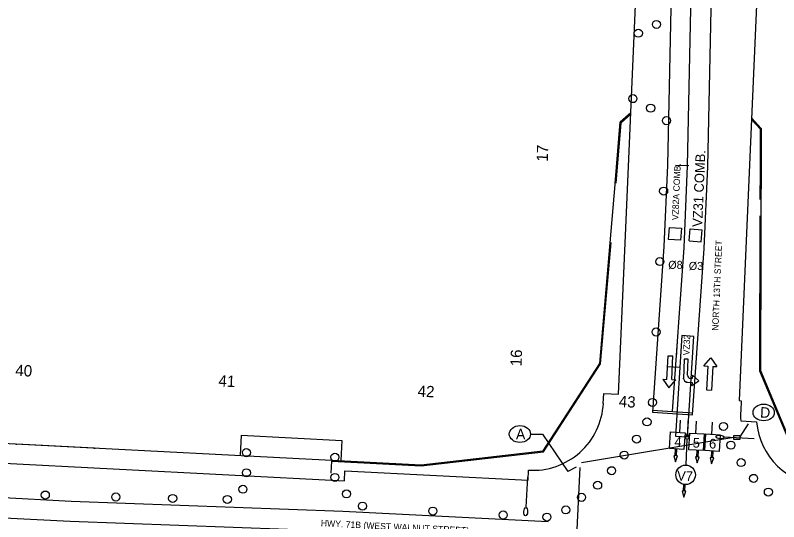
# Model space of a CAD drawing. Extents: x 0 to 1361828, y 0 to 1470398.
# Drawn here: x 683277 to 683656, y 735026.6 to 735277.9 of the extents above; entities that cross this region are included whole.
import ezdxf

# ---------------------------------------------------------------- set-up
doc = ezdxf.new("R2010")
doc.units = 0
for name, color, linetype in [('$', 7, 'Continuous'), ('Level 53', 7, 'Continuous'), ('MOT Stage 1', 7, 'Continuous'), ('MOT Stage 1 Lanes', 7, 'Continuous'), ('R_Horz Alg Station', 7, 'Continuous'), ('R_TYPE_A_CURB', 7, 'Continuous'), ('RW-EX', 7, 'Continuous'), ('RW-PR', 7, 'Continuous'), ('SIGNAL-EX', 7, 'Continuous'), ('SIGNAL-PLAN VIEW LABLES', 7, 'Continuous'), ('SIGNAL-PR', 7, 'Continuous'), ('TITEXT', 7, 'Continuous'), ('Video-Zones-pr', 7, 'Continuous')]:
    doc.layers.add(name, color=color, linetype=linetype)

# ---------------------------------------------------------------- blocks, each defined once
blk = doc.blocks.new('BAREL_1610')
at = {"layer": 'MOT Stage 1'}
blk.add_circle((0, 0.01), 2.88, dxfattribs=at)
blk = doc.blocks.new('BAREL_1611')
at = {"layer": 'MOT Stage 1'}
blk.add_circle((0, 0.01), 2.88, dxfattribs=at)
blk = doc.blocks.new('BAREL_1612')
at = {"layer": 'MOT Stage 1'}
blk.add_circle((0, 0.01), 2.88, dxfattribs=at)
blk = doc.blocks.new('BAREL_1613')
at = {"layer": 'MOT Stage 1'}
blk.add_circle((0, 0.01), 2.88, dxfattribs=at)
blk = doc.blocks.new('BAREL_1614')
at = {"layer": 'MOT Stage 1'}
blk.add_circle((0, 0.01), 2.88, dxfattribs=at)
blk = doc.blocks.new('BAREL_1654')
at = {"layer": 'MOT Stage 1'}
blk.add_circle((0, 0.01), 2.88, dxfattribs=at)
blk = doc.blocks.new('BAREL_1655')
at = {"layer": 'MOT Stage 1'}
blk.add_circle((0, 0.01), 2.88, dxfattribs=at)
blk = doc.blocks.new('BAREL_1656')
at = {"layer": 'MOT Stage 1'}
blk.add_circle((0, 0.01), 2.88, dxfattribs=at)
blk = doc.blocks.new('BAREL_1657')
at = {"layer": 'MOT Stage 1'}
blk.add_circle((0, 0.01), 2.88, dxfattribs=at)
blk = doc.blocks.new('BAREL_1658')
at = {"layer": 'MOT Stage 1'}
blk.add_circle((0, 0.01), 2.88, dxfattribs=at)
blk = doc.blocks.new('BAREL_1672')
at = {"layer": 'MOT Stage 1'}
blk.add_circle((0, 0.01), 2.88, dxfattribs=at)
blk = doc.blocks.new('BAREL_1673')
at = {"layer": 'MOT Stage 1'}
blk.add_circle((0, 0.01), 2.88, dxfattribs=at)
blk = doc.blocks.new('BAREL_1674')
at = {"layer": 'MOT Stage 1'}
blk.add_circle((0, 0.01), 2.88, dxfattribs=at)
blk = doc.blocks.new('BAREL_1675')
at = {"layer": 'MOT Stage 1'}
blk.add_circle((0, 0.01), 2.88, dxfattribs=at)
blk = doc.blocks.new('BAREL_1676')
at = {"layer": 'MOT Stage 1'}
blk.add_circle((0, 0.01), 2.88, dxfattribs=at)
blk = doc.blocks.new('BAREL_1677')
at = {"layer": 'MOT Stage 1'}
blk.add_circle((0, 0.01), 2.88, dxfattribs=at)
blk = doc.blocks.new('BAREL_1678')
at = {"layer": 'MOT Stage 1'}
blk.add_circle((0, 0.01), 2.88, dxfattribs=at)
blk = doc.blocks.new('BAREL_1679')
at = {"layer": 'MOT Stage 1'}
blk.add_circle((0, 0.01), 2.88, dxfattribs=at)
blk = doc.blocks.new('BAREL_1680')
at = {"layer": 'MOT Stage 1'}
blk.add_circle((0, 0.01), 2.88, dxfattribs=at)
blk = doc.blocks.new('SARROW_205')
at = {"layer": 'MOT Stage 1'}
for p, q in [((-6, -29.42), (-6, 0)), ((0, 0), (-6, 0)), ((0, -29.42), (0, 0)), ((-6, -29.42), (-11, -29.42)), ((-3, -39.81), (-11, -29.42)), ((5, -29.42), (-3, -39.81)), ((5, -29.42), (0, -29.42))]:
    blk.add_line(p, q, dxfattribs=at)
blk = doc.blocks.new('SARROW_206')
at = {"layer": 'MOT Stage 1'}
for p, q in [((-6, -29.42), (-6, 0)), ((0, 0), (-6, 0)), ((0, -29.42), (0, 0)), ((-6, -29.42), (-11, -29.42)), ((-3, -39.81), (-11, -29.42)), ((5, -29.42), (-3, -39.81)), ((5, -29.42), (0, -29.42))]:
    blk.add_line(p, q, dxfattribs=at)
blk = doc.blocks.new('BAREL_1708')
at = {"layer": 'MOT Stage 1'}
blk.add_circle((0, 0.01), 2.88, dxfattribs=at)
blk = doc.blocks.new('BAREL_1709')
at = {"layer": 'MOT Stage 1'}
blk.add_circle((0, 0.01), 2.88, dxfattribs=at)
blk = doc.blocks.new('BAREL_1710')
at = {"layer": 'MOT Stage 1'}
blk.add_circle((0, 0.01), 2.88, dxfattribs=at)
blk = doc.blocks.new('BAREL_1711')
at = {"layer": 'MOT Stage 1'}
blk.add_circle((0, 0.01), 2.88, dxfattribs=at)
blk = doc.blocks.new('BAREL_1712')
at = {"layer": 'MOT Stage 1'}
blk.add_circle((0, 0.01), 2.88, dxfattribs=at)
blk = doc.blocks.new('BAREL_1713')
at = {"layer": 'MOT Stage 1'}
blk.add_circle((0, 0.01), 2.88, dxfattribs=at)
blk = doc.blocks.new('BAREL_1714')
at = {"layer": 'MOT Stage 1'}
blk.add_circle((0, 0.01), 2.88, dxfattribs=at)
blk = doc.blocks.new('BAREL_1715')
at = {"layer": 'MOT Stage 1'}
blk.add_circle((0, 0.01), 2.88, dxfattribs=at)
blk = doc.blocks.new('BAREL_1716')
at = {"layer": 'MOT Stage 1'}
blk.add_circle((0, 0.01), 2.88, dxfattribs=at)
blk = doc.blocks.new('BAREL_1717')
at = {"layer": 'MOT Stage 1'}
blk.add_circle((0, 0.01), 2.88, dxfattribs=at)
blk = doc.blocks.new('BAREL_1718')
at = {"layer": 'MOT Stage 1'}
blk.add_circle((0, 0.01), 2.88, dxfattribs=at)
blk = doc.blocks.new('BAREL_1719')
at = {"layer": 'MOT Stage 1'}
blk.add_circle((0, 0.01), 2.88, dxfattribs=at)
blk = doc.blocks.new('BAREL_1724')
at = {"layer": 'MOT Stage 1'}
blk.add_circle((0, 0.01), 2.88, dxfattribs=at)
blk = doc.blocks.new('BAREL_1725')
at = {"layer": 'MOT Stage 1'}
blk.add_circle((0, 0.01), 2.88, dxfattribs=at)
blk = doc.blocks.new('BAREL_1726')
at = {"layer": 'MOT Stage 1'}
blk.add_circle((0, 0.01), 2.88, dxfattribs=at)
blk = doc.blocks.new('BAREL_1727')
at = {"layer": 'MOT Stage 1'}
blk.add_circle((0, 0.01), 2.88, dxfattribs=at)

msp = doc.modelspace()

# ---------------------------------------------------------------- linework, layer by layer
at = {"layer": 'Level 53'}
for p, q in [((683605.17, 735108.34), (683605.71, 735116.09)), ((683605.21, 735108.97), (683605.71, 735116.11)), ((683615.14, 735107.49), (683615.69, 735115.39))]:
    msp.add_line(p, q, dxfattribs=at)
at = {"layer": 'MOT Stage 1'}
for points in [[(683609.12, 735107.33), (683608.69, 735097.56), (683608.71, 735097.88)], [(683610.7, 735099.39), (683611.04, 735107.24), (683609.12, 735107.33)], [(683610.54, 735095.88), (683610.22, 735095.89), (683612.97, 735095.77), (683612.9, 735094.17), (683616.34, 735096.59), (683613.13, 735099.29), (683613.06, 735097.69), (683612.23, 735097.72)]]:
    msp.add_lwpolyline(points, dxfattribs=at)
for centre, radius in [((683610.63, 735097.79), 1.92), ((683612.29, 735099.32), 1.6)]:
    msp.add_arc(centre, radius, 177.5178, 267.5178, dxfattribs=at)
at = {"layer": 'MOT Stage 1 Lanes'}
for p, q in [((683124.65, 735046.17), (683304.73, 735036.86)), ((683124.13, 735036.18), (683304.21, 735026.87)), ((683304.73, 735036.86), (683439.64, 735031.89)), ((683439.64, 735031.89), (683541.55, 735026.66)), ((683304.21, 735026.87), (683439.13, 735021.9))]:
    msp.add_line(p, q, dxfattribs=at)
for points in [[(683604.91, 735398.45), (683600.74, 735203.61), (683598.98, 735163.25), (683593.24, 735081.04), (683613.19, 735079.65), (683618.95, 735162.12), (683620.73, 735202.96), (683624.91, 735398.02)], [(683603.28, 735081.34), (683608.96, 735162.68), (683610.73, 735203.28), (683614.91, 735398.23)], [(683593.31, 735082.04), (683613.26, 735080.64)]]:
    msp.add_lwpolyline(points, dxfattribs=at)
at = {"layer": 'R_Horz Alg Station'}
for points in [[(683604.74, 735203.6), (683611.4, 735203.31)], [(683600.38, 735103.7), (683607.04, 735103.4)]]:
    msp.add_lwpolyline(points, dxfattribs=at)
at = {"layer": 'R_TYPE_A_CURB'}
for p, q in [((683577.31, 735224.82), (683582.52, 735229.59)), ((683577.79, 735224.58), (683582.49, 735228.89)), ((683574.71, 735194.45), (683577.31, 735224.82)), ((683277.57, 735064.8), (683277.59, 735065.3)), ((683277.59, 735065.3), (683316.35, 735063.29)), ((683316.35, 735063.29), (683316.33, 735062.8))]:
    msp.add_line(p, q, dxfattribs=at)
for points in [[(683642.47, 735226.98), (683647.24, 735221.76), (683647.2, 735200.49)], [(683575.24, 735194.67), (683577.79, 735224.58)], [(683642.44, 735226.27), (683646.74, 735221.57), (683646.7, 735200.49)], [(683646.7, 735200.49), (683646.67, 735186.44)], [(683647.2, 735200.49), (683647.17, 735186.44)], [(683646.66, 735178.44), (683646.51, 735101.56), (683663.93, 735059.77), (683703.29, 735042.44), (683738.83, 735040.46), (683775.77, 735038.39)], [(683647.16, 735178.44), (683647.01, 735101.66), (683664.31, 735060.15), (683703.41, 735042.94), (683739.35, 735040.93), (683775.3, 735038.92)], [(683433.76, 735050.72), (683434.07, 735056.71), (683478.54, 735054.43), (683539.25, 735061.37), (683567.57, 735104.98), (683572.72, 735165.22)]]:
    msp.add_lwpolyline(points, dxfattribs=at)
at = {"layer": 'RW-EX'}
for p, q in [((683579.69, 735164.78), (683593.35, 735477.74)), ((683651.72, 735438.91), (683636.35, 735086.75)), ((683576.43, 735089.96), (683579.69, 735164.78)), ((683568.91, 735085.34), (683569.17, 735090.33)), ((683569.17, 735090.33), (683576.43, 735089.96)), ((683636.35, 735086.75), (683637.37, 735086.69)), ((683637.37, 735086.69), (683637.09, 735081.7)), ((683637.11, 735076.69), (683644.97, 735076.25)), ((682951.92, 735072.12), (683440.41, 735046.87)), ((683531.55, 735047.2), (683531.8, 735052.19)), ((683440.41, 735046.87), (683440.66, 735051.86)), ((683440.66, 735051.86), (683531.55, 735047.2))]:
    msp.add_line(p, q, dxfattribs=at)
for centre, radius, start, end in [((683533.96, 735087.13), 35, 266.468, 357.0668), ((683680.03, 735079.3), 43, 176.7989, 183.4763), ((683679.84, 735079.28), 35, 184.9566, 266.3951)]:
    msp.add_arc(centre, radius, start, end, dxfattribs=at)
at = {"layer": 'RW-PR'}
for p, q in [((683389.17, 735069.54), (683388.66, 735059.56)), ((683389.17, 735069.54), (683439.11, 735066.96)), ((683439.11, 735066.96), (683438.59, 735056.98))]:
    msp.add_line(p, q, dxfattribs=at)
for points in [[(683582.52, 735229.59), (683577.31, 735224.82), (683567.08, 735105.15), (683538.96, 735061.84)], [(683642.47, 735226.98), (683647.24, 735221.76), (683647.01, 735101.66), (683664.31, 735060.15)], [(682953.3, 735102.08), (682980.75, 735110.68), (682985.75, 735110.42), (682989.19, 735080.2), (683277.18, 735065.32), (683449.96, 735056.39), (683478.52, 735054.93), (683538.96, 735061.84)]]:
    msp.add_lwpolyline(points, dxfattribs=at)
at = {"layer": 'SIGNAL-EX'}
for points in [[(683640.74, 735075.18), (683636.7, 735068.73)], [(683633.68, 735068.46), (683558.1, 735055.78)], [(683555.49, 735053.7), (683551.34, 735051.57)], [(683553.48, 734971.62), (683557.44, 735053.56)]]:
    msp.add_lwpolyline(points, dxfattribs=at)
msp.add_lwpolyline([(683633.73, 735069.49), (683636.72, 735069.35), (683636.63, 735067.36), (683633.64, 735067.5)], close=True, dxfattribs=at)
at = {"layer": 'SIGNAL-PLAN VIEW LABLES'}
for points in [[(683606.99, 735077.02), (683606.68, 735070.89)], [(683610.86, 735076.77), (683610.62, 735070.65)], [(683614.98, 735076.51), (683614.66, 735070.41)], [(683622.96, 735076.01), (683622.65, 735069.98)], [(683532.78, 735070.07), (683538.78, 735070.07), (683551.34, 735051.57)], [(683610.3, 735067.7), (683609.79, 735054.76)], [(683604.44, 735059.37), (683603.93, 735059.4), (683604.7, 735056.4), (683605.78, 735059.3), (683605.28, 735059.33), (683605.45, 735062.68), (683604.61, 735062.73), (683604.44, 735059.37)], [(683604.61, 735062.73), (683604.44, 735059.37), (683603.93, 735059.4), (683604.7, 735056.4), (683605.78, 735059.3), (683605.28, 735059.33), (683605.45, 735062.68)], [(683615.22, 735058.74), (683614.72, 735058.77), (683615.49, 735055.77), (683616.56, 735058.67), (683616.06, 735058.7), (683616.23, 735062.05), (683615.39, 735062.1), (683615.22, 735058.74)], [(683615.39, 735062.1), (683615.22, 735058.74), (683614.72, 735058.77), (683615.49, 735055.77), (683616.56, 735058.67), (683616.06, 735058.7), (683616.23, 735062.05)], [(683622.37, 735058.35), (683621.87, 735058.38), (683622.64, 735055.39), (683623.71, 735058.29), (683623.21, 735058.31), (683623.38, 735061.67), (683622.54, 735061.71), (683622.37, 735058.35)], [(683622.54, 735061.71), (683622.37, 735058.35), (683621.87, 735058.38), (683622.64, 735055.39), (683623.71, 735058.29), (683623.21, 735058.31), (683623.38, 735061.67)], [(683608.58, 735041.83), (683608.08, 735041.85), (683608.91, 735038.87), (683609.93, 735041.79), (683609.42, 735041.8), (683609.53, 735045.16), (683608.69, 735045.19), (683608.58, 735041.83)], [(683608.69, 735045.19), (683608.58, 735041.83), (683608.08, 735041.85), (683608.91, 735038.87), (683609.93, 735041.79), (683609.42, 735041.8), (683609.53, 735045.16)]]:
    msp.add_lwpolyline(points, dxfattribs=at)
for points in [[(683608.93, 735062.48), (683601.8, 735062.9), (683602.29, 735071.15), (683609.48, 735070.72)], [(683610.62, 735070.65), (683611.54, 735067.64), (683609.46, 735067.74)], [(683618.43, 735061.92), (683611.31, 735062.34), (683611.8, 735070.59), (683618.99, 735070.16)], [(683626.42, 735061.49), (683619.3, 735061.91), (683619.79, 735070.16), (683626.98, 735069.73)]]:
    msp.add_lwpolyline(points, close=True, dxfattribs=at)
msp.add_circle((683609.76, 735049.91), 4.85, dxfattribs=at)
for centre in [(683648.5, 735080.87), (683527.51, 735070.13)]:
    msp.add_ellipse(centre, major_axis=(-5.27, 0), ratio=0.790685, dxfattribs=at)
at = {"layer": 'SIGNAL-PR'}
for p, q in [((683643.85, 735067.77), (683628.87, 735068.53)), ((683531.29, 735048.78), (683530.51, 735033.8))]:
    msp.add_line(p, q, dxfattribs=at)
for centre, major_axis in [((683626.85, 735068.64), (2.02, -0.1)), ((683530.4, 735031.6), (0.11, 2.02))]:
    msp.add_ellipse(centre, major_axis=major_axis, ratio=0.447722, dxfattribs=at)
at = {"layer": 'Video-Zones-pr'}
for points in [[(683607.29, 735166.27), (683601.3, 735166.69), (683601.72, 735172.67), (683607.7, 735172.25), (683607.29, 735166.27)], [(683611.54, 735165.97), (683611.96, 735171.96)], [(683611.96, 735171.96), (683617.94, 735171.54)], [(683617.52, 735165.55), (683617.94, 735171.54)], [(683611.54, 735165.97), (683617.52, 735165.55)]]:
    msp.add_lwpolyline(points, dxfattribs=at)
msp.add_lwpolyline([(683607.85, 735118.98), (683604.69, 735069.08), (683610.67, 735068.7), (683613.83, 735118.6)], close=True, dxfattribs=at)

# ---------------------------------------------------------------- block references
at = {"layer": 'MOT Stage 1'}
for name, p, xscale, yscale, rotation in [('BAREL_1727', (683595.28, 735273.39), 0.6945420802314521, 0.6945420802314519, 87.04179557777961), ('BAREL_1726', (683586.29, 735269.03), 0.6945420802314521, 0.6945420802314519, 87.04179557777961), ('BAREL_1725', (683583.6, 735236.56), 0.6945420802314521, 0.6945420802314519, 87.04179557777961), ('BAREL_1724', (683592.41, 735231.83), 0.6945420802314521, 0.6945420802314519, 87.04179557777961), ('BAREL_1719', (683600.25, 735225.63), 0.6945420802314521, 0.6945420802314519, 87.04179557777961), ('BAREL_1718', (683598.85, 735190.66), 0.6945420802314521, 0.6945420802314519, 87.04179557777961), ('BAREL_1717', (683596.99, 735155.71), 0.6945420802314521, 0.6945420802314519, 87.04179557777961), ('BAREL_1716', (683595.11, 735120.76), 0.6945420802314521, 0.6945420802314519, 87.04179557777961), ('SARROW_205', (683601.06, 735108.99), 0.4000000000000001, -0.4000000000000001, 177.22923073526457), ('SARROW_206', (683620.19, 735092.11), 0.3999999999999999, 0.3999999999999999, 176.69984902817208), ('BAREL_1715', (683593.31, 735085.8), 0.6945420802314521, 0.6945420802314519, 87.04179557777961), ('BAREL_1714', (683590.6, 735076.18), 0.6945420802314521, 0.6945420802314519, 87.04179557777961), ('BAREL_1658', (683628.56, 735073.9), 0.6945420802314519, 0.694542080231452, 102.17652807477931), ('BAREL_1713', (683585.42, 735067.62), 0.6945420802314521, 0.6945420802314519, 87.04179557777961), ('BAREL_1657', (683632.27, 735064.61), 0.6945420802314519, 0.694542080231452, 102.17652807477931), ('BAREL_1610', (683391.74, 735060.9), 0.6945420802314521, 0.6945420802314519, 87.04179557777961), ('BAREL_1611', (683435.68, 735058.63), 0.6945420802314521, 0.6945420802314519, 87.04179557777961), ('BAREL_1712', (683579.31, 735059.71), 0.6945420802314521, 0.6945420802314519, 87.04179557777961), ('BAREL_1656', (683637.29, 735055.97), 0.6945420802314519, 0.694542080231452, 102.17652807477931), ('BAREL_1612', (683391.74, 735050.9), 0.6945420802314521, 0.6945420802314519, 87.04179557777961), ('BAREL_1711', (683573.02, 735051.94), 0.6945420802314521, 0.6945420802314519, 87.04179557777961), ('BAREL_1614', (683435.68, 735048.63), 0.6945420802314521, 0.6945420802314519, 87.04179557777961), ('BAREL_1655', (683643.51, 735048.14), 0.6945420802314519, 0.694542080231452, 102.17652807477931), ('BAREL_1613', (683390.02, 735042.75), 0.6945420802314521, 0.6945420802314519, 87.04179557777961), ('BAREL_1710', (683566.09, 735044.72), 0.6945420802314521, 0.6945420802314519, 87.04179557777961), ('BAREL_1672', (683291.9, 735039.87), 0.6945420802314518, 0.6945420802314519, 116.71114235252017), ('BAREL_1673', (683326.89, 735038.91), 0.6945420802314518, 0.6945420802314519, 116.71114235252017), ('BAREL_1674', (683355.14, 735038.17), 0.6945420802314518, 0.6945420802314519, 116.71114235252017), ('BAREL_1676', (683441.43, 735040.45), 0.6945420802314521, 0.6945420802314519, 87.04179557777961), ('BAREL_1709', (683558.08, 735038.74), 0.6945420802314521, 0.6945420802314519, 87.04179557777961), ('BAREL_1654', (683650.85, 735041.34), 0.6945420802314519, 0.694542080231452, 102.17652807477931), ('BAREL_1675', (683382.26, 735037.71), 0.6945420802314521, 0.6945420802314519, 87.04179557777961), ('BAREL_1677', (683449.37, 735034.37), 0.6945420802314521, 0.6945420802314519, 87.04179557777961), ('BAREL_1678', (683484.29, 735031.91), 0.6945420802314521, 0.6945420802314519, 87.04179557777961), ('BAREL_1708', (683550.28, 735032.48), 0.6945420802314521, 0.6945420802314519, 87.04179557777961), ('BAREL_1679', (683519.23, 735029.97), 0.6945420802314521, 0.6945420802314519, 87.04179557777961), ('BAREL_1680', (683540.93, 735028.94), 0.6945420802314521, 0.6945420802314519, 87.04179557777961)]:
    msp.add_blockref(name, p, dxfattribs=dict(at, xscale=xscale, yscale=yscale, rotation=rotation))

# ---------------------------------------------------------------- texts
at = {"layer": '$'}
for s, height, rotation, p in [('17', 5.6, 88.3887, (683541.37, 735205.23)), ('VZ31 COMB.', 4.8, 87.5006, (683617.95, 735172.8)), ('VZ82A COMB.', 3.2, 87.5006, (683606.12, 735176.18)), ('NORTH 13TH STREET', 3.2, 87.5995, (683626.03, 735121.35)), ('VZ32', 3.2, 87.5006, (683611.65, 735109.11)), ('16', 5.6, 88.3887, (683528.36, 735103.71)), ('40', 5.6, 357.0415, (683276.92, 735099.04)), ('41', 5.6, 357.0415, (683377.75, 735093.83)), ('42', 5.6, 357.0415, (683476.63, 735088.74)), ('43', 5.6, 357.0415, (683576.49, 735083.61)), ('HWY. 71B (WEST WALNUT STREET)', 3.2, 357.0637, (683428.62, 735024.4))]:
    msp.add_text(s, height=height, rotation=rotation, dxfattribs=at).set_placement(p)
at = {"layer": 'SIGNAL-PLAN VIEW LABLES'}
for s, height, p in [('D', 5.2, (683646.63, 735078.36)), ('4', 4.8, (683604.1, 735064.03)), ('5', 4.8, (683613.2, 735063.48)), ('6', 4.8, (683621.3, 735063.05)), ('V7', 4.8, (683605.42, 735047.13))]:
    msp.add_text(s, height=height, rotation=357.0414, dxfattribs=at).set_placement(p)
msp.add_text('A', height=5.2, dxfattribs=at).set_placement((683525.53, 735067.53))
at = {"layer": 'TITEXT'}
for s, p in [('%%C8', (683601.15, 735152.07)), ('%%C3', (683611.34, 735151.54))]:
    msp.add_text(s, height=4, dxfattribs=at).set_placement(p)

doc.saveas('drawing.dxf')
